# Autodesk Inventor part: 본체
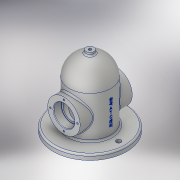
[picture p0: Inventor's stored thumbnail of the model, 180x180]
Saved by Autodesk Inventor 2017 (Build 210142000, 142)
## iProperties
Created: 2019-11
Part Number: 본체
Material: Aluminum 6061
Document SubType Name: Modeling
Designer: 1-19-lg
Density: 2.7 g/cm^3
Appearance: Aluminum - Flat
Mass: 1106.12 g
Surface Area: 883.25 cm^2
Volume: 409.674 cm^3
Author: 1-19-lg
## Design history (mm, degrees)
sketch "Sketch1"
  geometry: C1 r 70 at (0, 0); 1 further point
  constraints: 1 centre point, 1 coincident
  dimensions: "d0" = 140 diameter of C1
extrude "Extrusion1" new body sketch "Sketch1" distance "d1" = 10; taper "d2" = 0 deg
sketch "Sketch3"
  geometry: L1 (70, 10)-(-70, 10) reference; L2 (-70, 0)-(70, 0) reference; L3 (0, 10)-(-40, 10); L4 (-40, 10)-(-40, 90); L5 (0, -27.657)-(0, 165.941) reference; L6 (0, 130)-(0, 10); A1 r 40 centre (0, 90) between (0, 130) and (-40, 90); 1 further point
  constraints: 6 end point, 3 point on line, 2 point on circle, 1 centre point, 1 horizontal, 1 perpendicular
  dimensions: "d5" = 40 radius of A1; "d6" = 90 distance from line of L4.end L2
revolve "Revolution1" sketch "Sketch3" stored, may be unused: angle "d7" = 90 deg
sketch "Sketch4"
  geometry: C1 r 31 at (0, 50); 1 further point
  constraints: 1 centre point
  dimensions: "d8" = 62 diameter of C1; "d9" = 50 distance of C1.centre point (0, 0)
extrude "Extrusion2" join sketch "Sketch4" stored distance "d10" = 100; taper "d11" = 0 deg
sketch "Sketch5"
  geometry: C1 r 30 at (0, 0); 1 further point
  constraints: 1 centre point, 1 coincident
  dimensions: "d12" = 60 diameter of C1
extrude "Extrusion3" cut sketch "Sketch5" distance "d13" = 90; taper "d14" = 0 deg
sketch "Sketch6"
  geometry: C1 r 20 at (0, 0); 1 further point
  constraints: 1 centre point
  dimensions: "d15" = 40 diameter of C1
extrude "Extrusion4" cut sketch "Sketch6" distance "d16" = 15; taper "d17" = 0 deg
sketch "Sketch7"
  geometry: C1 r 20 at (0, 0); 1 further point
  constraints: 1 centre point
  dimensions: "d18" = 40 diameter of C1
extrude "Extrusion5" cut sketch "Sketch7" distance "d19" = 15; taper "d20" = 0 deg
sketch "Sketch8"
  geometry: C1 r 16.5 at (0, 0); C2 r 20 at (0, 0) reference; C3 r 31 at (0, 0) reference; 1 further point
  constraints: 1 centre point, 1 coincident
  dimensions: "d21" = 33 diameter of C1
extrude "Extrusion6" cut sketch "Sketch8" stored distance "d22" = 15; taper "d23" = 0 deg
sketch "Sketch14"
  geometry: L1 (30, 90)-(-30, 90) reference; L2 (0, 90)-(0, 120); L3 (0, 90)-(30, 90); L4 (40, 90)-(-40, 90) reference; A1 r 30 centre (0, 90) between (30, 90) and (0, 120); 1 further point
  constraints: 4 end point, 2 point on circle, 2 point on line, 1 centre point, 1 collinear, 1 midpoint, 1 vertical
revolve "Revolution2" sketch "Sketch14" stored, may be unused: angle "d56" = 90 deg
sketch "Sketch9"
  geometry: A1 r 26 centre (0, 0) between (0, 26) and (-26, 0); 3 further points
  constraints: 4 point on circle, 1 centre point
  dimensions: "d25" = 52 diameter of A1
hole "Hole1" sketch "Sketch9" at (0, 26), (-26, 0), (26, 0), (0, -26) diameter "d26" = 3.242; stored, may be unused: countersink angle "d30" = 90 deg, drill point angle "d32" = 118 deg; dims "d27" = 8, "d28" = 4, "d29" = 2, "d31" = 10
mirror "Mirror1"
sketch "Sketch10"
  geometry: C1 r 4.5 at (55, 0); C2 r 4.5 at (-55, 0); A1 r 55 centre (0, 0) between (55, 0) and (-55, 0); 1 further point
  constraints: 3 centre point, 2 point on circle, 1 coincident, 1 equal radius
  dimensions: "d33" = 110 diameter of A1; "d34" = 9 diameter of C2
extrude "Extrusion7" cut sketch "Sketch10" stored distance "d35" = 15; taper "d36" = 0 deg
workplane "Work Plane3"
sketch "Sketch12"
  geometry: C1 r 7.5 at (0, 0); 1 further point
  constraints: 1 centre point, 1 coincident
  dimensions: "d39" = 15 diameter of C1
extrude "Extrusion8" join sketch "Sketch12" stored distance "d40" = 15; taper "d41" = 0 deg
sketch "Sketch13"
  geometry: 2 further points
  constraints: 1 coincident
hole "Hole2" sketch "Sketch13" at (0, 0) diameter "d42" = 5.188; stored, may be unused: countersink angle "d46" = 90 deg, drill point angle "d48" = 118 deg; dims "d43" = 30, "d44" = 4, "d45" = 2, "d47" = 16
fillet "Fillet1" dims "d37" = 3, "d55" = 0.3
chamfer "Chamfer1" distance "d52" = 1; stored, may be unused: second distance "d53" = 2, angle "d54" = 45 deg
workplane "Work Plane1"
sketch "Sketch11"
  geometry: L1 (-15.847, 35.625)-(15.847, 35.625); L2 (15.847, 35.625)-(15.847, -34.965); L3 (15.847, -34.965)-(-15.847, -34.965); L4 (-15.847, -34.965)-(-15.847, 35.625); L5 (0, -76)-(0, 106) reference; L6 (-15.847, 0.33)-(15.847, 0.33); L7 (-70, -50)-(70, -50) reference; 1 further point
  constraints: 2 end point, 2 midpoint, 3 other
  dimensions: "d49" = 50.33 distance between parallel lines of L6 L7
emboss "Emboss1" sketch "Sketch11" dims "d12" = 60, "d50" = 0.5, "d51" = 0
body "Solid1"
node "Projected Loop1"
node "Projected Loop2"
other parameters: "d38" = 135
